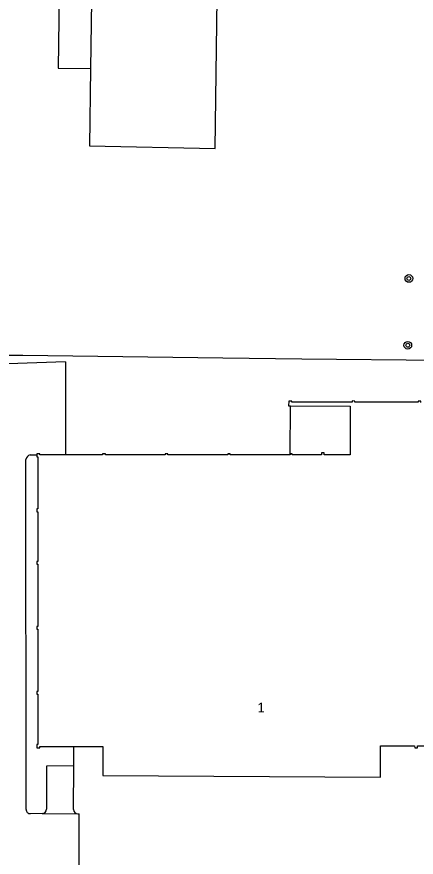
# Model space of a CAD drawing. Extents: x 132573 to 132944, y 398226 to 398676.
# Drawn here: x 132640.6 to 132682.1, y 398350.8 to 398438.1 of the extents above; entities that cross this region are included whole.
import ezdxf

# ---------------------------------------------------------------- set-up
doc = ezdxf.new("R2010")
doc.units = 0
for name, color, linetype in [('gg-afsc-hekwerk', 7, 'Continuous'), ('gg-anno-huisnummerreeks BGT', 7, 'Continuous'), ('gg-bbg-gedigitaliseerde bebouwing', 7, 'Continuous'), ('gg-bbg-hoofdgebouw', 7, 'Continuous'), ('gg-bbg-luifel en loopbrug', 7, 'Continuous'), ('gg-knt-verharding', 7, 'Continuous'), ('gg-knt-verharding nz', 7, 'Continuous'), ('gt-grn-vlakafsluiter', 7, 'Continuous'), ('gt-symb-boom', 7, 'Continuous')]:
    doc.layers.add(name, color=color, linetype=linetype)

msp = doc.modelspace()

# ---------------------------------------------------------------- linework, layer by layer
at = {"layer": 'gg-afsc-hekwerk'}
msp.add_line((132647.086, 398349.104), (132647.073, 398355.334), dxfattribs=at)
msp.add_lwpolyline([(132604.511, 398403.424), (132608.788, 398403.371), (132617.481, 398403.23), (132626.206, 398403.178), (132635.061, 398402.95), (132641.245, 398402.951), (132661.988, 398402.675), (132670.216, 398402.551), (132684.626, 398402.413)], dxfattribs=at)
at = {"layer": 'gg-bbg-gedigitaliseerde bebouwing'}
msp.add_lwpolyline([(132649.533, 398362.215), (132649.533, 398359.326), (132678.366, 398359.127), (132678.362, 398362.387)], dxfattribs=at)
at = {"layer": 'gg-bbg-hoofdgebouw'}
for points in [[(132648.26, 398432.699), (132648.148, 398424.658), (132661.196, 398424.405), (132661.807, 398468.582), (132648.76, 398468.747), (132648.657, 398460.626)], [(132645.776, 398446.807), (132648.456, 398446.77), (132648.26, 398432.699)], [(132682.553, 398398.031), (132682.557, 398398.172), (132682.276, 398398.179), (132682.276, 398398.071), (132675.719, 398398.07), (132675.719, 398398.185), (132675.434, 398398.19), (132675.435, 398398.07), (132669.151, 398398.07), (132669.153, 398398.181), (132668.839, 398398.185), (132668.833, 398397.675), (132669.023, 398397.674)], [(132669.023, 398397.674), (132675.236, 398397.649), (132675.215, 398392.602), (132672.512, 398392.585), (132672.51, 398392.805), (132672.235, 398392.806), (132672.239, 398392.595), (132669.215, 398392.593), (132669.215, 398392.7), (132669.002, 398392.703)], [(132642.697, 398392.593), (132642.698, 398392.401), (132642.806, 398392.401), (132642.805, 398386.979), (132642.688, 398386.979), (132642.692, 398386.691), (132642.805, 398386.69), (132642.804, 398381.527), (132642.691, 398381.527), (132642.696, 398381.239), (132642.804, 398381.239), (132642.802, 398374.772), (132642.693, 398374.772), (132642.695, 398374.489), (132642.802, 398374.489), (132642.801, 398368.035), (132642.695, 398368.035), (132642.696, 398367.751), (132642.8, 398367.751), (132642.799, 398362.534), (132642.69, 398362.534), (132642.686, 398362.198), (132642.989, 398362.202), (132642.989, 398362.316), (132646.517, 398362.321)], [(132645.675, 398392.597), (132643.003, 398392.597), (132643.003, 398392.709), (132642.697, 398392.709), (132642.697, 398392.593)], [(132669.002, 398392.703), (132668.989, 398392.703), (132668.989, 398392.593), (132662.752, 398392.594), (132662.752, 398392.705), (132662.503, 398392.707), (132662.503, 398392.594), (132656.285, 398392.595), (132656.285, 398392.694), (132656.027, 398392.697), (132656.027, 398392.595), (132649.805, 398392.596), (132649.805, 398392.702), (132649.525, 398392.699), (132649.525, 398392.596), (132645.675, 398392.597)], [(132678.362, 398362.387), (132681.915, 398362.389), (132681.916, 398362.198), (132682.212, 398362.199), (132682.212, 398362.389), (132688.613, 398362.393), (132688.613, 398362.195), (132688.922, 398362.197), (132688.92, 398362.516), (132688.751, 398362.516), (132688.746, 398380.873), (132688.924, 398380.873), (132688.921, 398381.17), (132688.815, 398381.169), (132688.78, 398386.056), (132688.897, 398386.057), (132688.898, 398386.171), (132692.416, 398386.167), (132692.416, 398386.051), (132692.726, 398386.048), (132692.731, 398386.369), (132692.612, 398386.369), (132692.61, 398387.061)], [(132646.517, 398362.321), (132649.533, 398362.326), (132649.533, 398362.215)]]:
    msp.add_lwpolyline(points, dxfattribs=at)
at = {"layer": 'gg-bbg-luifel en loopbrug'}
msp.add_line((132669.002, 398392.703), (132669.023, 398397.674), dxfattribs=at)
msp.add_lwpolyline([(132648.657, 398460.626), (132645.274, 398460.671), (132644.899, 398432.744), (132648.26, 398432.699)], dxfattribs=at)
at = {"layer": 'gg-knt-verharding'}
for p, q in [((132642.005, 398392.59), (132642.697, 398392.593)), ((132641.575, 398355.792), (132641.551, 398392.126)), ((132646.499, 398355.786), (132646.52, 398360.309)), ((132643.229, 398355.355), (132642.007, 398355.345)), ((132643.229, 398355.355), (132646.946, 398355.329)), ((132646.946, 398355.329), (132647.073, 398355.334))]:
    msp.add_line(p, q, dxfattribs=at)
for points in [[(132645.674, 398402.24), (132626.792, 398401.58), (132626.926, 398397.736)], [(132646.52, 398360.309), (132643.689, 398360.268), (132643.688, 398355.807)]]:
    msp.add_lwpolyline(points, dxfattribs=at)
for centre, radius, start, end in [((132642.138, 398392.005), 0.6, 102.85039, 168.39784), ((132642.01, 398355.781), 0.436, 178.48889, 269.55581), ((132643.224, 398355.82), 0.465, 270.67327, 358.44624), ((132646.964, 398355.794), 0.465, 180.93574, 267.7967)]:
    msp.add_arc(centre, radius, start, end, dxfattribs=at)
at = {"layer": 'gg-knt-verharding nz'}
msp.add_line((132645.674, 398402.24), (132645.675, 398392.597), dxfattribs=at)
at = {"layer": 'gt-grn-vlakafsluiter'}
msp.add_line((132646.52, 398360.309), (132646.517, 398362.321), dxfattribs=at)
at = {"layer": 'gt-symb-boom'}
for centre, radius in [((132681.315, 398410.906), 0.4), ((132681.315, 398410.906), 0.2), ((132681.203, 398403.974), 0.4), ((132681.203, 398403.974), 0.2)]:
    msp.add_circle(centre, radius, dxfattribs=at)

# ---------------------------------------------------------------- texts
at = {"layer": 'gg-anno-huisnummerreeks BGT'}
msp.add_text('1', height=1, dxfattribs=at).set_placement((132665.608, 398365.88))

doc.saveas('drawing.dxf')
